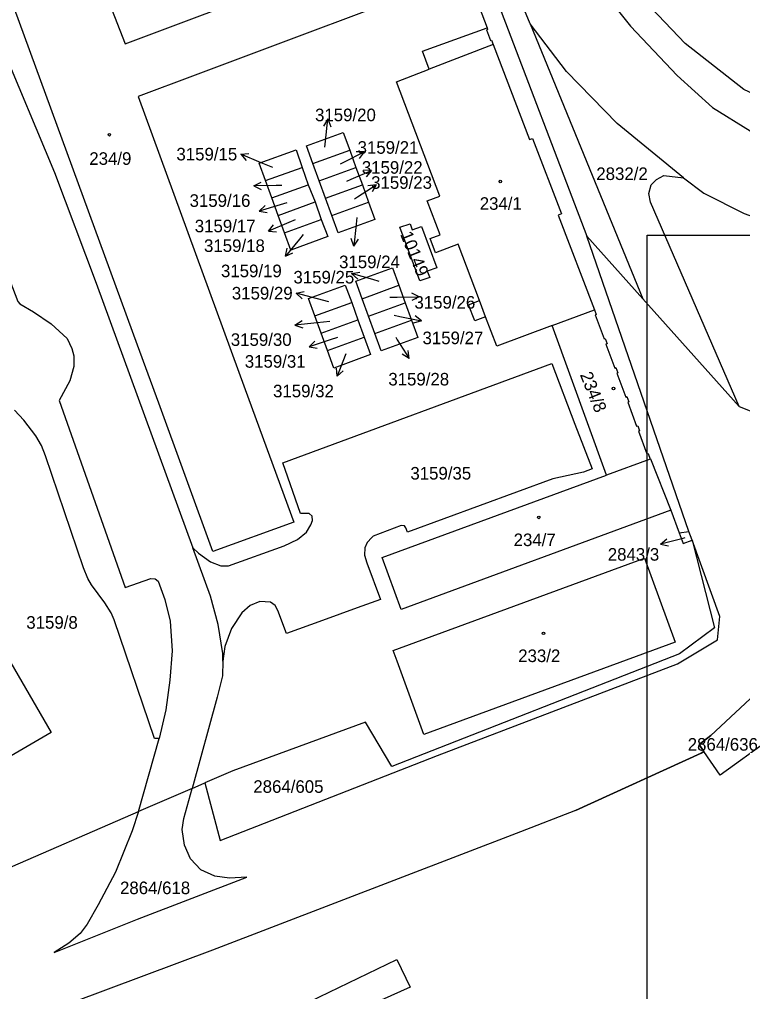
# Model space of a CAD drawing. Extents: x -564952 to -564307, y -1202373 to -1201847.
# Drawn here: x -564730.1 to -564632.5, y -1202091.3 to -1201959.8 of the extents above; entities that cross this region are included whole.
import ezdxf

# ---------------------------------------------------------------- set-up
doc = ezdxf.new("R2010")
doc.units = 0
for name, color, linetype in [('Hranice parcel', 7, 'Continuous'), ('Parcelní čísla', 7, 'Continuous'), ('Pop  PČ popisy', 7, 'Continuous'), ('Vnitřní kresba', 7, 'Continuous'), ('Vrstva 63', 7, 'Continuous'), ('Značky budov', 7, 'Continuous')]:
    doc.layers.add(name, color=color, linetype=linetype)

msp = doc.modelspace()

# ---------------------------------------------------------------- linework, layer by layer
at = {"layer": 'Hranice parcel'}
for p, q in [((-564668.12, -1201950.64), (-564653.5, -1201989.14)), ((-564661.15, -1201960.44), (-564645.92, -1201997.62)), ((-564690.51, -1201979.3), (-564685.53, -1201977.5)), ((-564685.53, -1201977.5), (-564684.68, -1201979.84)), ((-564689.66, -1201981.66), (-564690.51, -1201979.3)), ((-564696.9, -1201981.63), (-564691.97, -1201979.84)), ((-564691.97, -1201979.84), (-564691.12, -1201982.19)), ((-564689.66, -1201981.66), (-564684.68, -1201979.84)), ((-564684.68, -1201979.84), (-564683.82, -1201982.19)), ((-564696.05, -1201983.98), (-564696.9, -1201981.63)), ((-564688.8, -1201984), (-564689.66, -1201981.66)), ((-564696.05, -1201983.98), (-564691.12, -1201982.19)), ((-564691.12, -1201982.19), (-564690.21, -1201984.52)), ((-564688.8, -1201984), (-564683.82, -1201982.19)), ((-564683.82, -1201982.19), (-564682.97, -1201984.54)), ((-564695.19, -1201986.33), (-564696.05, -1201983.98)), ((-564695.19, -1201986.33), (-564690.21, -1201984.52)), ((-564690.21, -1201984.52), (-564689.36, -1201986.87)), ((-564687.95, -1201986.35), (-564688.8, -1201984)), ((-564687.95, -1201986.35), (-564682.97, -1201984.54)), ((-564694.34, -1201988.68), (-564695.19, -1201986.33)), ((-564694.34, -1201988.68), (-564689.36, -1201986.87)), ((-564653.5, -1201989.14), (-564645.92, -1201997.62)), ((-564639.69, -1202029.09), (-564653.5, -1201989.14)), ((-564683.85, -1201997.6), (-564678.88, -1201995.79)), ((-564678.88, -1201995.79), (-564678.02, -1201998.14)), ((-564683, -1201999.95), (-564683.85, -1201997.6)), ((-564645.92, -1201997.62), (-564632.9, -1202012.18)), ((-564690.24, -1201999.92), (-564685.26, -1201998.11)), ((-564685.26, -1201998.11), (-564684.41, -1202000.46)), ((-564683, -1201999.95), (-564678.02, -1201998.14)), ((-564678.02, -1201998.14), (-564677.17, -1202000.49)), ((-564689.39, -1202002.28), (-564690.24, -1201999.92)), ((-564682.15, -1202002.3), (-564683, -1201999.95)), ((-564658.18, -1202001.22), (-564652.47, -1201999.1)), ((-564689.39, -1202002.28), (-564684.41, -1202000.46)), ((-564684.41, -1202000.46), (-564683.56, -1202002.81)), ((-564682.15, -1202002.3), (-564677.17, -1202000.49)), ((-564650.82, -1202021.45), (-564658.18, -1202001.22)), ((-564688.54, -1202004.62), (-564689.39, -1202002.28)), ((-564688.54, -1202004.62), (-564683.56, -1202002.81)), ((-564644.94, -1202019.28), (-564650.82, -1202021.45)), ((-564642.16, -1202026.18), (-564678.58, -1202039.62)), ((-564642.16, -1202026.18), (-564641.02, -1202029.26)), ((-564641.02, -1202029.26), (-564639.69, -1202029.09)), ((-564639.28, -1202030.26), (-564639.69, -1202029.09)), ((-564714.05, -1202066.95), (-564711.28, -1202057.08)), ((-564701.32, -1202061.43), (-564705.09, -1202063.07)), ((-564706.83, -1202063.82), (-564705.09, -1202063.07)), ((-564706.83, -1202063.82), (-564714.05, -1202066.95)), ((-564748.68, -1202081.97), (-564714.05, -1202066.95))]:
    msp.add_line(p, q, dxfattribs=at)
for points in [[(-564686.16, -1201871.23), (-564677.08, -1201895.29), (-564660.17, -1201939.88), (-564659.23, -1201942.17), (-564652.34, -1201954.8), (-564647.57, -1201960.74), (-564641.3, -1201967.43), (-564636.51, -1201971.74), (-564631.4, -1201974.9), (-564623.41, -1201978.76)], [(-564661.15, -1201960.44), (-564670.99, -1201936.66), (-564694.16, -1201875.63)], [(-564711.3, -1202011.73), (-564714.18, -1202003.86), (-564737.5, -1201940.24), (-564726.36, -1201936.19)], [(-564726.36, -1201936.19), (-564715.86, -1201963.16), (-564672.37, -1201946.79)], [(-564743.87, -1201974.68), (-564742.68, -1201973.7), (-564742.16, -1201972.86), (-564756.86, -1201945.42), (-564755.16, -1201944.44), (-564755.45, -1201943.97), (-564751.11, -1201941.46), (-564745.96, -1201938.44), (-564740.22, -1201948.79), (-564732.79, -1201962.98), (-564725.4, -1201980.52), (-564719.8, -1201995.48), (-564706.71, -1202031.28)], [(-564596.05, -1201977.38), (-564604.58, -1201977.37), (-564614.37, -1201976.21), (-564623.15, -1201973.61), (-564632.26, -1201969.32), (-564640.22, -1201963.11), (-564646.58, -1201956.32), (-564653.95, -1201945.36)], [(-564669.89, -1201953.65), (-564706.41, -1201967.36), (-564714.12, -1201970.26), (-564699.64, -1202009.87)], [(-564669.89, -1201953.65), (-564669.13, -1201955.68), (-564668.99, -1201955.63), (-564666.96, -1201960.96)], [(-564674.77, -1201966.57), (-564675.67, -1201964.13), (-564666.96, -1201960.96)], [(-564666.96, -1201960.96), (-564666.9, -1201961.19), (-564667.04, -1201961.24), (-564666.5, -1201962.69), (-564666.36, -1201962.64), (-564666.14, -1201963.23), (-564661.24, -1201976.08), (-564660.82, -1201975.92), (-564656.92, -1201986.14), (-564657.34, -1201986.3), (-564652.47, -1201999.1)], [(-564640.45, -1201981.26), (-564649.4, -1201973.92), (-564656.22, -1201966.86), (-564661.15, -1201960.44)], [(-564674.66, -1201989.46), (-564673.31, -1201988.97), (-564675.04, -1201984.36), (-564673.36, -1201983.73), (-564679.22, -1201968.26), (-564674.77, -1201966.57)], [(-564690.51, -1201979.3), (-564691.37, -1201976.95), (-564686.39, -1201975.14), (-564685.53, -1201977.5)], [(-564696.9, -1201981.63), (-564697.76, -1201979.28), (-564692.78, -1201977.47), (-564691.97, -1201979.84)], [(-564738.81, -1201981.26), (-564737.28, -1201981.76), (-564736.22, -1201982.93), (-564735.6, -1201984.35), (-564730.37, -1201997.98), (-564730.11, -1201998.29), (-564728.24, -1201999.36), (-564725.88, -1202000.98), (-564723.7, -1202002.98), (-564723.06, -1202004.34), (-564722.79, -1202005.32), (-564722.8, -1202006.77), (-564723.36, -1202008.7), (-564724.79, -1202011.36), (-564715.88, -1202036.65), (-564712.4, -1202035.41), (-564711.8, -1202035.46), (-564711.42, -1202035.78), (-564710.52, -1202038.26), (-564709.8, -1202041.19), (-564709.53, -1202045.2), (-564709.81, -1202049.19), (-564710.38, -1202053.2), (-564711.28, -1202057.08)], [(-564632.9, -1202012.18), (-564644.89, -1201984.55), (-564645.1, -1201983.38), (-564644.79, -1201982.21), (-564644.06, -1201981.48), (-564643.08, -1201980.96), (-564640.45, -1201981.26)], [(-564640.45, -1201981.26), (-564637.68, -1201983.33), (-564632.21, -1201986.09), (-564621.75, -1201989.88), (-564611.99, -1201991.88), (-564598.44, -1201992.53), (-564592.52, -1201992.17), (-564572.99, -1201990.58)], [(-564682.97, -1201984.54), (-564682.11, -1201986.9), (-564687.1, -1201988.71), (-564687.95, -1201986.35)], [(-564689.36, -1201986.87), (-564688.5, -1201989.21), (-564693.49, -1201991.02), (-564694.34, -1201988.68)], [(-564676.05, -1201995.18), (-564678.75, -1201987.93), (-564677.35, -1201987.47), (-564677.08, -1201988.29), (-564675.81, -1201987.83), (-564673.77, -1201993.41), (-564675.04, -1201993.86), (-564674.72, -1201994.71), (-564676.05, -1201995.18)], [(-564670.86, -1201990.22), (-564673.93, -1201991.38), (-564674.66, -1201989.46)], [(-564658.18, -1202001.22), (-564665.67, -1202004), (-564667.17, -1202000.05), (-564668.64, -1202000.6), (-564669.47, -1201998.42), (-564668, -1201997.86), (-564670.86, -1201990.22)], [(-564683.85, -1201997.6), (-564684.71, -1201995.25), (-564679.73, -1201993.44), (-564678.88, -1201995.79)], [(-564690.24, -1201999.92), (-564691.1, -1201997.57), (-564686.12, -1201995.76), (-564685.26, -1201998.11)], [(-564655, -1202066.79), (-564638.03, -1202059.06), (-564637.69, -1202058.81), (-564638.33, -1202057.87), (-564636.74, -1202056.66), (-564621.41, -1202042.36), (-564620.58, -1202043.17), (-564610.49, -1202033.02), (-564584.31, -1202015.23), (-564579.06, -1202011.62), (-564576.04, -1202009.54), (-564575.81, -1202009.88), (-564559.51, -1202001.15), (-564554.04, -1201999.85), (-564546.86, -1201999.32), (-564540.29, -1202000.14), (-564533.65, -1202003.36), (-564528.41, -1202007.65), (-564524, -1202013.27)], [(-564652.47, -1201999.1), (-564652.23, -1201999.73), (-564652.37, -1201999.78), (-564651.16, -1202003.03), (-564651.02, -1202002.98), (-564650.76, -1202003.69), (-564650.9, -1202003.74), (-564649.69, -1202006.97), (-564649.55, -1202006.92), (-564649.3, -1202007.6), (-564649.44, -1202007.66), (-564648.23, -1202010.89), (-564648.09, -1202010.84), (-564647.83, -1202011.54), (-564647.97, -1202011.59), (-564646.76, -1202014.84), (-564646.62, -1202014.79), (-564646.36, -1202015.47), (-564646.5, -1202015.52), (-564645.36, -1202018.59), (-564645.22, -1202018.54), (-564644.94, -1202019.28)], [(-564677.17, -1202000.49), (-564676.31, -1202002.84), (-564681.29, -1202004.65), (-564682.15, -1202002.3)], [(-564683.56, -1202002.81), (-564682.71, -1202005.16), (-564687.69, -1202006.97), (-564688.54, -1202004.62)], [(-564706.71, -1202031.28), (-564705.96, -1202031.99), (-564704.35, -1202033.17), (-564702.93, -1202033.73), (-564701.92, -1202033.71), (-564694.37, -1202031), (-564692.56, -1202030.14), (-564691.38, -1202029.17), (-564690.8, -1202028.17), (-564690.57, -1202027.61), (-564690.58, -1202026.98), (-564690.99, -1202026.62), (-564692.16, -1202026.62), (-564694.55, -1202019.79), (-564658.22, -1202006.34), (-564655.12, -1202014.55), (-564652.79, -1202020.62), (-564653.96, -1202021.05), (-564658.06, -1202021.97), (-564677.71, -1202029.18), (-564677.93, -1202028.58), (-564678.14, -1202028.33), (-564678.57, -1202028.28), (-564682.34, -1202029.71), (-564682.55, -1202029.87), (-564683.17, -1202030.58), (-564683.49, -1202031.3), (-564683.53, -1202032.28), (-564683.19, -1202033.3), (-564681.37, -1202038.27), (-564684.52, -1202039.4), (-564689.21, -1202041.12), (-564694.08, -1202042.88), (-564695.23, -1202039.76), (-564695.59, -1202039.09), (-564696.21, -1202038.63), (-564697.68, -1202038.54), (-564698.99, -1202039.09), (-564700.12, -1202040.08), (-564701.49, -1202042.19), (-564702.38, -1202044.62), (-564702.69, -1202046.59)], [(-564699.64, -1202009.87), (-564693.09, -1202027.81), (-564704, -1202031.8), (-564711.3, -1202011.73)], [(-564632.9, -1202012.18), (-564611.28, -1202020.76), (-564606.29, -1202019.78)], [(-564711.28, -1202057.08), (-564711.89, -1202057.07), (-564717.33, -1202041), (-564717.74, -1202040.08), (-564718.61, -1202038.7), (-564720.39, -1202036.28), (-564720.92, -1202035.43), (-564721.5, -1202034.01), (-564726.63, -1202018.86), (-564727.16, -1202017.44), (-564727.95, -1202016.15), (-564729.54, -1202014), (-564730.82, -1202012.69)], [(-564644.94, -1202019.28), (-564644.87, -1202019.26), (-564642.16, -1202026.18)], [(-564678.58, -1202039.62), (-564681.14, -1202032.61), (-564650.82, -1202021.45)], [(-564641.02, -1202029.26), (-564640.48, -1202030.71), (-564639.28, -1202030.26)], [(-564705.09, -1202063.07), (-564703.05, -1202070.87), (-564673.66, -1202059.38), (-564641.23, -1202046.96), (-564635.84, -1202043.71), (-564635.54, -1202040.56), (-564639.28, -1202030.26)], [(-564639.28, -1202030.26), (-564636.25, -1202042.12), (-564640.99, -1202045.63), (-564679.85, -1202060.87), (-564683.39, -1202054.87), (-564701.32, -1202061.43)], [(-564702.69, -1202046.59), (-564702.67, -1202045.58), (-564703.28, -1202041.64), (-564704.33, -1202037.8), (-564706.71, -1202031.28)], [(-564760.54, -1202044.37), (-564739.77, -1202032.27), (-564725.85, -1202056.25), (-564767.37, -1202080.44)], [(-564641.55, -1202044.04), (-564675.51, -1202056.52), (-564679.11, -1202046.62), (-564679.66, -1202045.18), (-564645.68, -1202032.66), (-564641.55, -1202044.04)], [(-564620.58, -1202043.17), (-564621.41, -1202042.36), (-564636.74, -1202056.66), (-564638.33, -1202057.87), (-564637.69, -1202058.81)], [(-564702.69, -1202046.59), (-564702.72, -1202048.57), (-564703.43, -1202051.47), (-564706.83, -1202063.82)], [(-564628.87, -1202057.25), (-564635.48, -1202062.04), (-564637.69, -1202058.81)], [(-564637.69, -1202058.81), (-564638.03, -1202059.06), (-564655, -1202066.79), (-564662.43, -1202069.69), (-564704.06, -1202085.69), (-564722.99, -1202092.74), (-564729.95, -1202095.67), (-564736.84, -1202098.72), (-564741.32, -1202100.95), (-564768.52, -1202116.71), (-564777.25, -1202121.88), (-564783.74, -1202125.64), (-564785.97, -1202126.79), (-564816.39, -1202144.49)], [(-564701.75, -1202075.95), (-564703.77, -1202075.67), (-564705.62, -1202074.81), (-564707.02, -1202073.32), (-564707.86, -1202071.49), (-564708.14, -1202069.39), (-564707.94, -1202067.86), (-564706.83, -1202063.82)], [(-564714.05, -1202066.95), (-564714.91, -1202069.57), (-564717.19, -1202075.12), (-564719.5, -1202079.57), (-564721, -1202082.19), (-564721.93, -1202083.42), (-564723.48, -1202084.75)], [(-564723.48, -1202084.75), (-564725.45, -1202085.98), (-564714.18, -1202081.49), (-564699.41, -1202075.82), (-564701.75, -1202075.95)], [(-564697.44, -1202095.78), (-564679.17, -1202086.93), (-564677.37, -1202090.67), (-564696.04, -1202099.05), (-564697.44, -1202095.78)]]:
    msp.add_lwpolyline(points, dxfattribs=at)
at = {"layer": 'Pop  PČ popisy'}
for p, q in [((-564688.48, -1201973.3), (-564689.08, -1201974.25)), ((-564688.79, -1201976.29), (-564688.48, -1201973.3)), ((-564688.48, -1201973.3), (-564688.08, -1201974.35)), ((-564688.87, -1201977.11), (-564688.79, -1201976.29)), ((-564700.25, -1201978.04), (-564699.14, -1201977.97)), ((-564697.49, -1201979.21), (-564700.25, -1201978.04)), ((-564700.25, -1201978.04), (-564699.53, -1201978.89)), ((-564686.25, -1201979.08), (-564683.55, -1201977.76)), ((-564683.55, -1201977.76), (-564684.67, -1201977.75)), ((-564683.55, -1201977.76), (-564684.23, -1201978.65)), ((-564695.92, -1201979.87), (-564697.49, -1201979.21)), ((-564686.79, -1201979.35), (-564686.25, -1201979.08)), ((-564685.32, -1201981.45), (-564682.56, -1201980.28)), ((-564682.56, -1201980.28), (-564683.68, -1201980.21)), ((-564682.56, -1201980.28), (-564683.28, -1201981.13)), ((-564698.48, -1201982.36), (-564697.49, -1201981.84)), ((-564685.9, -1201981.7), (-564685.32, -1201981.45)), ((-564695.48, -1201982.31), (-564698.48, -1201982.36)), ((-564698.48, -1201982.36), (-564697.47, -1201982.85)), ((-564694.69, -1201982.3), (-564695.48, -1201982.31)), ((-564684.46, -1201983.83), (-564681.94, -1201982.2)), ((-564681.94, -1201982.2), (-564683.06, -1201982.32)), ((-564681.94, -1201982.2), (-564682.51, -1201983.16)), ((-564694.01, -1201984.62), (-564694.91, -1201984.9)), ((-564684.88, -1201984.11), (-564684.46, -1201983.83)), ((-564694.91, -1201984.9), (-564697.78, -1201985.78)), ((-564697.78, -1201985.78), (-564696.97, -1201985.01)), ((-564697.78, -1201985.78), (-564696.68, -1201985.96)), ((-564692.91, -1201986.95), (-564693.76, -1201987.3)), ((-564684.55, -1201986.63), (-564684.64, -1201987.51)), ((-564693.76, -1201987.3), (-564696.52, -1201988.47)), ((-564696.52, -1201988.47), (-564695.8, -1201987.62)), ((-564696.52, -1201988.47), (-564695.41, -1201988.54)), ((-564684.64, -1201987.51), (-564684.95, -1201990.5)), ((-564692.33, -1201989.54), (-564694.22, -1201991.87)), ((-564691.81, -1201988.91), (-564692.33, -1201989.54)), ((-564684.95, -1201990.5), (-564685.35, -1201989.45)), ((-564684.95, -1201990.5), (-564684.35, -1201989.55)), ((-564694.22, -1201991.87), (-564693.98, -1201990.78)), ((-564694.22, -1201991.87), (-564693.2, -1201991.41)), ((-564685.28, -1201994.19), (-564684.17, -1201993.99)), ((-564682.39, -1201995.02), (-564685.28, -1201994.19)), ((-564685.28, -1201994.19), (-564684.45, -1201994.95)), ((-564681.53, -1201995.26), (-564682.39, -1201995.02)), ((-564692.77, -1201996.85), (-564691.67, -1201996.63)), ((-564689.87, -1201997.63), (-564692.77, -1201996.85)), ((-564692.77, -1201996.85), (-564691.93, -1201997.6)), ((-564688.34, -1201998.04), (-564689.87, -1201997.63)), ((-564680.09, -1201997.4), (-564679.13, -1201997.38)), ((-564679.13, -1201997.38), (-564676.13, -1201997.33)), ((-564676.13, -1201997.33), (-564677.14, -1201996.84)), ((-564676.13, -1201997.33), (-564677.12, -1201997.85)), ((-564679.52, -1201999.82), (-564678.74, -1201999.99)), ((-564678.74, -1201999.99), (-564675.81, -1202000.61)), ((-564675.81, -1202000.61), (-564676.68, -1201999.92)), ((-564692.92, -1202001.16), (-564691.97, -1202000.56)), ((-564689.93, -1202000.85), (-564692.92, -1202001.16)), ((-564692.92, -1202001.16), (-564691.87, -1202001.56)), ((-564688.19, -1202000.67), (-564689.93, -1202000.85)), ((-564675.81, -1202000.61), (-564676.89, -1202000.9)), ((-564687.16, -1202002.86), (-564688.16, -1202003.18)), ((-564679.3, -1202002.82), (-564679.1, -1202003.15)), ((-564688.16, -1202003.18), (-564691.01, -1202004.11)), ((-564691.01, -1202004.11), (-564690.22, -1202003.32)), ((-564691.01, -1202004.11), (-564689.91, -1202004.27)), ((-564679.1, -1202003.15), (-564677.51, -1202005.7)), ((-564686.14, -1202005.29), (-564687.21, -1202008.09)), ((-564686.05, -1202005.04), (-564686.14, -1202005.29)), ((-564677.51, -1202005.7), (-564678.46, -1202005.11)), ((-564677.51, -1202005.7), (-564677.62, -1202004.58)), ((-564687.21, -1202008.09), (-564687.32, -1202006.98)), ((-564687.21, -1202008.09), (-564686.39, -1202007.34)), ((-564640.64, -1202030.05), (-564643.55, -1202030.78)), ((-564643.55, -1202030.78), (-564642.7, -1202030.05)), ((-564640.26, -1202029.95), (-564640.64, -1202030.05)), ((-564643.55, -1202030.78), (-564642.46, -1202031.02))]:
    msp.add_line(p, q, dxfattribs=at)
at = {"layer": 'Vnitřní kresba'}
for p, q in [((-564666.14, -1201963.23), (-564674.77, -1201966.57)), ((-564667.17, -1202000.05), (-564668, -1201997.86))]:
    msp.add_line(p, q, dxfattribs=at)
at = {"layer": 'Vrstva 63'}
msp.add_lwpolyline([(-564540.34, -1202137.49), (-564645.34, -1202137.49), (-564645.34, -1201988.99), (-564540.34, -1201988.99)], close=True, dxfattribs=at)
at = {"layer": 'Značky budov'}
for centre in [(-564718, -1201975.43), (-564665.18, -1201981.76), (-564649.88, -1202009.75), (-564659.99, -1202027.17), (-564659.34, -1202042.84)]:
    msp.add_circle(centre, 0.175, dxfattribs=at)

# ---------------------------------------------------------------- texts
at = {"layer": 'Parcelní čísla'}
for s, p in [('3159/20', (-564690.21, -1201973.6)), ('3159/21', (-564684.46, -1201978)), ('234/9', (-564720.71, -1201979.5)), ('3159/15', (-564708.94, -1201978.9)), ('3159/22', (-564683.89, -1201980.7)), ('2832/2', (-564652.21, -1201981.55)), ('3159/23', (-564682.63, -1201982.74)), ('3159/16', (-564707.16, -1201985.18)), ('234/1', (-564667.96, -1201985.58)), ('3159/17', (-564706.46, -1201988.62)), ('3159/18', (-564705.21, -1201991.28)), ('3159/24', (-564686.96, -1201993.47)), ('3159/19', (-564702.92, -1201994.69)), ('3159/25', (-564693.13, -1201995.54)), ('3159/29', (-564701.45, -1201997.7)), ('3159/26', (-564676.78, -1201998.94)), ('3159/30', (-564701.59, -1202003.98)), ('3159/27', (-564675.69, -1202003.75)), ('3159/31', (-564699.7, -1202006.93)), ('3159/28', (-564680.31, -1202009.33)), ('3159/32', (-564695.88, -1202010.93)), ('3159/35', (-564677.33, -1202022.05)), ('234/7', (-564663.38, -1202031.05)), ('2843/3', (-564650.66, -1202033.02)), ('3159/8', (-564729.22, -1202042.22)), ('233/2', (-564662.76, -1202046.73)), ('2864/636', (-564639.86, -1202058.71)), ('2864/605', (-564698.55, -1202064.41)), ('2864/618', (-564716.56, -1202078.11))]:
    msp.add_text(s, height=1.7, dxfattribs=at).set_placement(p)
for s, p in [('10149', (-564678.74, -1201988.88)), ('234/8', (-564654.45, -1202007.88))]:
    msp.add_text(s, height=1.7, rotation=292, dxfattribs=at).set_placement(p)

doc.saveas('drawing.dxf')
